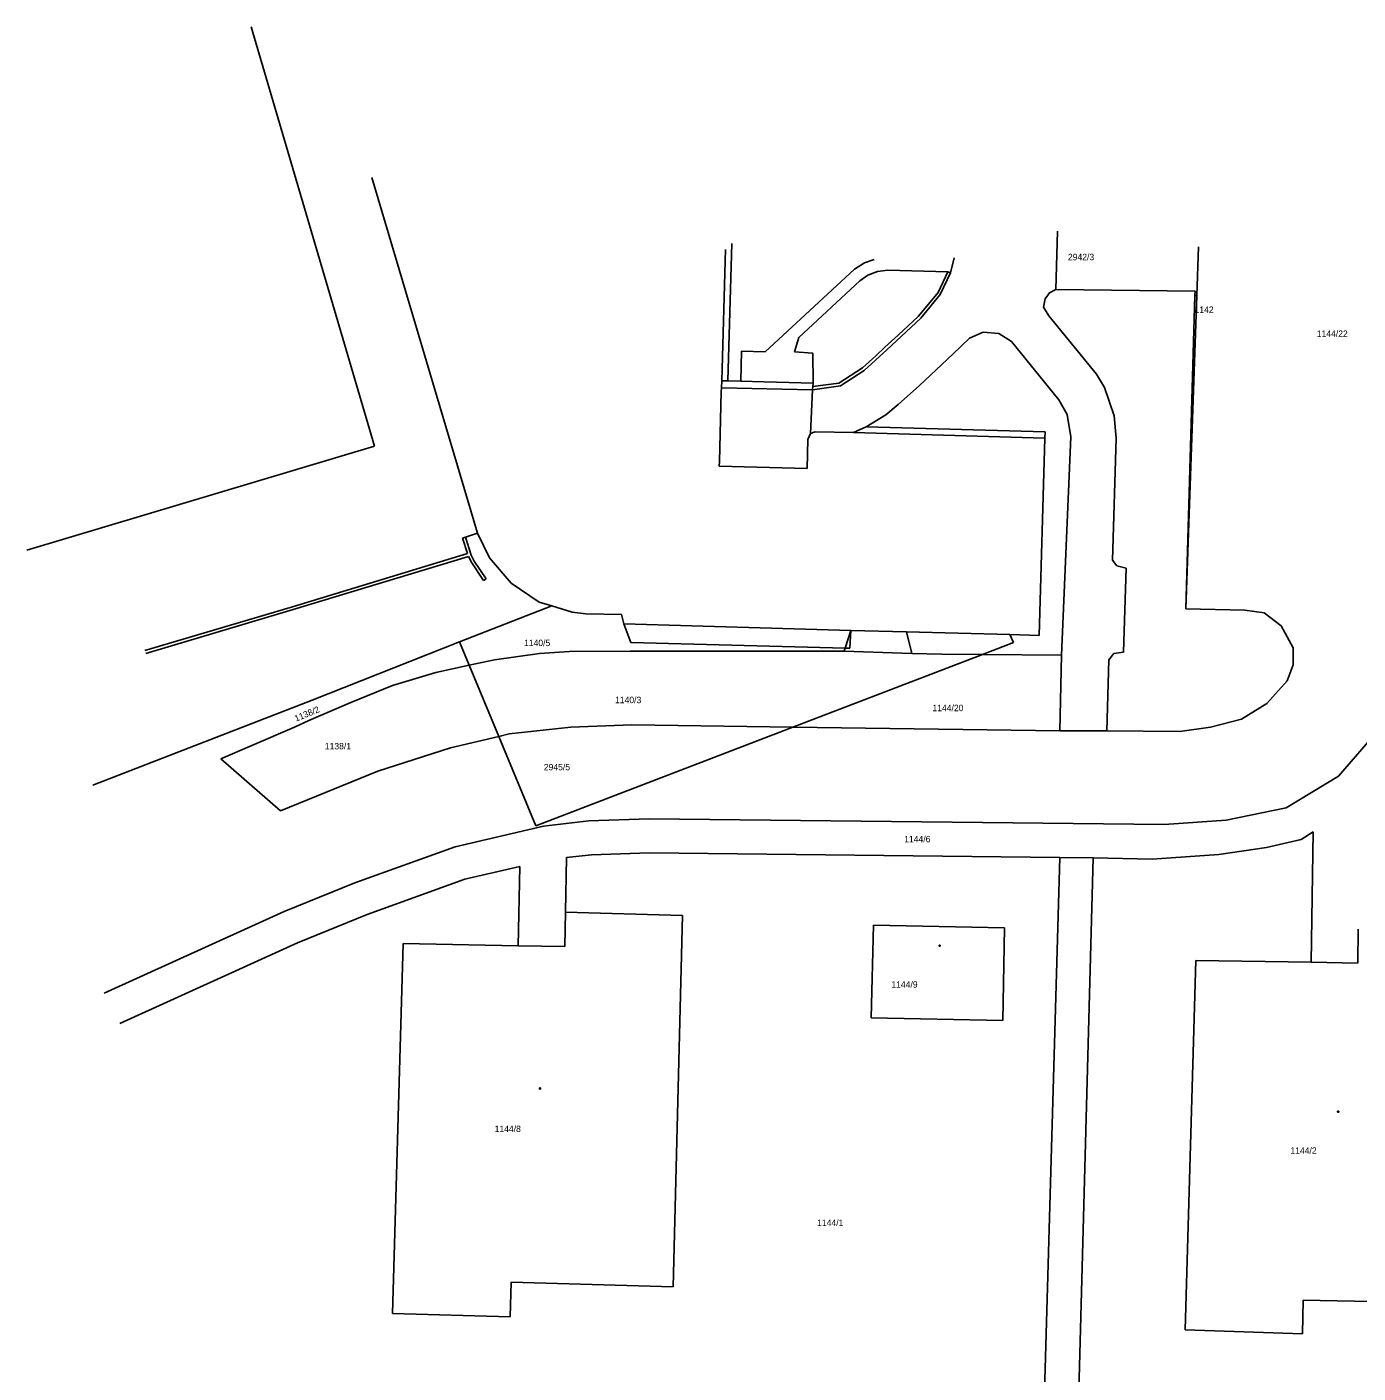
# Model space of a CAD drawing. Extents: x -609709 to -609357, y -1051535 to -1051131.
# Drawn here: x -609705.8 to -609617.6, y -1051228.1 to -1051138.9 of the extents above; entities that cross this region are included whole.
import ezdxf

# ---------------------------------------------------------------- set-up
doc = ezdxf.new("R2010")
doc.units = 0
doc.layers.add('Vrstva 10', color=7, linetype='Continuous')

msp = doc.modelspace()

# ---------------------------------------------------------------- linework, layer by layer
at = {"layer": 'Vrstva 10'}
for p, q in [((-609690.91, -1051138.88), (-609682.72, -1051166.66)), ((-609682.91, -1051148.86), (-609675.9, -1051172.42)), ((-609637.59, -1051156.27), (-609637.48, -1051152.42)), ((-609659.72, -1051162.34), (-609659.46, -1051153.63)), ((-609659.32, -1051162.34), (-609659.05, -1051153.24)), ((-609628.23, -1051156.67), (-609628.12, -1051153.46)), ((-609656.84, -1051160.41), (-609650.92, -1051154.94)), ((-609650.92, -1051154.94), (-609650.25, -1051154.52)), ((-609650.25, -1051154.52), (-609649.61, -1051154.3)), ((-609644.57, -1051155.17), (-609644.32, -1051154.19)), ((-609654.61, -1051159.46), (-609650.58, -1051155.71)), ((-609650.58, -1051155.71), (-609650.05, -1051155.32)), ((-609650.05, -1051155.32), (-609649.41, -1051155.08)), ((-609649.41, -1051155.08), (-609648.71, -1051154.99)), ((-609648.71, -1051154.99), (-609644.74, -1051155.1)), ((-609645.39, -1051156.48), (-609644.74, -1051155.1)), ((-609645.24, -1051156.61), (-609644.57, -1051155.17)), ((-609644.74, -1051155.1), (-609644.57, -1051155.17)), ((-609646.68, -1051158.04), (-609645.39, -1051156.48)), ((-609646.53, -1051158.17), (-609645.24, -1051156.61)), ((-609638.29, -1051156.9), (-609638, -1051156.5)), ((-609638, -1051156.5), (-609637.59, -1051156.27)), ((-609637.59, -1051156.27), (-609628.36, -1051156.39)), ((-609628.96, -1051177.44), (-609628.23, -1051156.67)), ((-609628.96, -1051177.44), (-609628.37, -1051156.67)), ((-609628.37, -1051156.67), (-609628.36, -1051156.39)), ((-609628.37, -1051156.67), (-609628.23, -1051156.67)), ((-609638.4, -1051157.45), (-609638.29, -1051156.9)), ((-609638.4, -1051157.45), (-609638.04, -1051158.03)), ((-609648.78, -1051160.28), (-609646.53, -1051158.17)), ((-609648.03, -1051159.31), (-609646.68, -1051158.04)), ((-609638.04, -1051158.03), (-609634.89, -1051161.9)), ((-609648.91, -1051160.11), (-609648.03, -1051159.31)), ((-609643.31, -1051159.5), (-609642.4, -1051159.11)), ((-609642.4, -1051159.11), (-609641.36, -1051159.2)), ((-609641.36, -1051159.2), (-609640.51, -1051159.73)), ((-609654.89, -1051160.42), (-609654.61, -1051159.46)), ((-609650.28, -1051161.64), (-609648.78, -1051160.28)), ((-609649.52, -1051160.67), (-609648.91, -1051160.11)), ((-609644.4, -1051160.56), (-609643.31, -1051159.5)), ((-609640.51, -1051159.73), (-609637.39, -1051163.58)), ((-609658.46, -1051162.36), (-609658.4, -1051160.36)), ((-609658.4, -1051160.36), (-609656.84, -1051160.41)), ((-609654.89, -1051160.42), (-609653.69, -1051160.5)), ((-609653.69, -1051160.5), (-609653.67, -1051162.48)), ((-609650.39, -1051161.47), (-609649.52, -1051160.67)), ((-609646.61, -1051162.65), (-609644.4, -1051160.56)), ((-609651.97, -1051162.49), (-609650.39, -1051161.47)), ((-609651.86, -1051162.66), (-609650.28, -1051161.64)), ((-609634.89, -1051161.9), (-609634.36, -1051162.77)), ((-609659.75, -1051163.07), (-609659.73, -1051162.8)), ((-609659.73, -1051162.8), (-609659.72, -1051162.34)), ((-609659.73, -1051162.8), (-609653.71, -1051162.93)), ((-609659.72, -1051162.34), (-609659.32, -1051162.34)), ((-609659.32, -1051162.34), (-609658.46, -1051162.36)), ((-609658.46, -1051162.36), (-609656.93, -1051162.39)), ((-609656.93, -1051162.39), (-609655.26, -1051162.45)), ((-609655.26, -1051162.45), (-609653.67, -1051162.48)), ((-609653.84, -1051165.82), (-609653.71, -1051162.93)), ((-609653.71, -1051162.93), (-609651.86, -1051162.66)), ((-609653.71, -1051162.93), (-609653.69, -1051162.7)), ((-609653.69, -1051162.7), (-609653.67, -1051162.48)), ((-609653.69, -1051162.7), (-609651.97, -1051162.49)), ((-609648.02, -1051163.9), (-609646.61, -1051162.65)), ((-609634.36, -1051162.77), (-609633.71, -1051164.66)), ((-609659.87, -1051167.67), (-609659.75, -1051163.07)), ((-609637.39, -1051163.58), (-609636.84, -1051164.56)), ((-609650.15, -1051165.39), (-609648.85, -1051164.58)), ((-609648.85, -1051164.58), (-609648.02, -1051163.9)), ((-609636.84, -1051164.56), (-609636.59, -1051166.05)), ((-609633.71, -1051164.66), (-609633.59, -1051166.14)), ((-609650.99, -1051165.76), (-609650.15, -1051165.39)), ((-609650.15, -1051165.39), (-609638.3, -1051165.72)), ((-609654.07, -1051168.15), (-609654.02, -1051166.21)), ((-609654.02, -1051166.21), (-609653.84, -1051165.82)), ((-609653.84, -1051165.82), (-609653.52, -1051165.72)), ((-609653.52, -1051165.72), (-609650.99, -1051165.76)), ((-609650.99, -1051165.76), (-609638.32, -1051166.12)), ((-609638.69, -1051179.2), (-609638.32, -1051166.12)), ((-609638.32, -1051166.12), (-609638.3, -1051165.72)), ((-609637.2, -1051180.5), (-609636.59, -1051166.05)), ((-609633.82, -1051174.22), (-609633.59, -1051166.14)), ((-609705.76, -1051173.56), (-609682.72, -1051166.66)), ((-609659.88, -1051167.99), (-609659.87, -1051167.67)), ((-609659.88, -1051167.99), (-609654.07, -1051168.15)), ((-609676.9, -1051172.76), (-609676.71, -1051172.69)), ((-609676.9, -1051172.76), (-609676.57, -1051173.77)), ((-609676.71, -1051172.69), (-609675.9, -1051172.42)), ((-609676.71, -1051172.69), (-609676.32, -1051173.88)), ((-609675.9, -1051172.42), (-609675.11, -1051174.06)), ((-609688.17, -1051177.3), (-609676.57, -1051173.77)), ((-609688.11, -1051177.49), (-609676.5, -1051173.97)), ((-609676.5, -1051173.97), (-609676.29, -1051174.4)), ((-609676.32, -1051173.88), (-609676.13, -1051174.29)), ((-609676.29, -1051174.4), (-609675.51, -1051175.56)), ((-609676.13, -1051174.29), (-609675.34, -1051175.45)), ((-609675.11, -1051174.06), (-609673.67, -1051175.74)), ((-609633.82, -1051174.22), (-609633.55, -1051174.59)), ((-609675.51, -1051175.56), (-609675.34, -1051175.45)), ((-609633.55, -1051174.59), (-609632.93, -1051174.74)), ((-609633.09, -1051180.31), (-609632.93, -1051174.74)), ((-609673.67, -1051175.74), (-609671.81, -1051177)), ((-609671.81, -1051177), (-609670.97, -1051177.25)), ((-609697.94, -1051180.21), (-609688.17, -1051177.3)), ((-609697.89, -1051180.4), (-609688.11, -1051177.49)), ((-609677.1, -1051179.63), (-609670.97, -1051177.25)), ((-609670.97, -1051177.25), (-609669.64, -1051177.65)), ((-609669.64, -1051177.65), (-609668.72, -1051177.78)), ((-609668.72, -1051177.78), (-609666.37, -1051177.81)), ((-609666.37, -1051177.81), (-609666.2, -1051178.44)), ((-609628.96, -1051177.44), (-609625.06, -1051177.52)), ((-609625.06, -1051177.52), (-609623.78, -1051177.7)), ((-609623.78, -1051177.7), (-609622.65, -1051178.57)), ((-609666.2, -1051178.44), (-609665.75, -1051179.68)), ((-609666.2, -1051178.44), (-609651.17, -1051178.87)), ((-609651.55, -1051180.04), (-609651.17, -1051178.87)), ((-609651.24, -1051180.05), (-609651.17, -1051178.87)), ((-609651.17, -1051178.87), (-609647.47, -1051178.96)), ((-609647.47, -1051178.96), (-609647.12, -1051180.39)), ((-609647.47, -1051178.96), (-609640.62, -1051179.15)), ((-609622.65, -1051178.57), (-609621.86, -1051180.03)), ((-609686.86, -1051183.49), (-609677.1, -1051179.63)), ((-609677.1, -1051179.63), (-609676.45, -1051181.18)), ((-609665.75, -1051179.68), (-609651.55, -1051180.04)), ((-609642.45, -1051180.46), (-609640.39, -1051179.67)), ((-609640.62, -1051179.15), (-609640.39, -1051179.67)), ((-609640.62, -1051179.15), (-609638.69, -1051179.2)), ((-609674.77, -1051180.82), (-609671.8, -1051180.4)), ((-609671.8, -1051180.4), (-609669.81, -1051180.26)), ((-609669.81, -1051180.26), (-609665.79, -1051180.25)), ((-609665.79, -1051180.25), (-609651.61, -1051180.24)), ((-609655.01, -1051185.28), (-609642.45, -1051180.46)), ((-609651.61, -1051180.24), (-609651.55, -1051180.04)), ((-609651.61, -1051180.24), (-609647.12, -1051180.39)), ((-609651.55, -1051180.04), (-609651.24, -1051180.05)), ((-609647.12, -1051180.39), (-609645.13, -1051180.44)), ((-609645.13, -1051180.44), (-609642.45, -1051180.46)), ((-609642.45, -1051180.46), (-609637.2, -1051180.5)), ((-609637.32, -1051185.53), (-609637.2, -1051180.5)), ((-609634.2, -1051185.52), (-609634.06, -1051180.81)), ((-609634.06, -1051180.81), (-609633.73, -1051180.39)), ((-609633.73, -1051180.39), (-609633.09, -1051180.31)), ((-609621.86, -1051180.03), (-609621.86, -1051181.15)), ((-609681.53, -1051182.51), (-609678.66, -1051181.66)), ((-609678.66, -1051181.66), (-609676.45, -1051181.18)), ((-609676.45, -1051181.18), (-609674.77, -1051180.82)), ((-609676.45, -1051181.18), (-609674.49, -1051185.89)), ((-609622.26, -1051182.21), (-609621.86, -1051181.15)), ((-609684.3, -1051183.65), (-609681.53, -1051182.51)), ((-609623.6, -1051183.71), (-609622.26, -1051182.21)), ((-609701.4, -1051189.13), (-609686.86, -1051183.49)), ((-609687.08, -1051184.84), (-609685.23, -1051184.04)), ((-609685.23, -1051184.04), (-609684.3, -1051183.65)), ((-609625.28, -1051184.75), (-609623.6, -1051183.71)), ((-609690.86, -1051186.49), (-609688.02, -1051185.27)), ((-609688.02, -1051185.27), (-609687.08, -1051184.84)), ((-609669.73, -1051185.29), (-609665.67, -1051185.13)), ((-609665.67, -1051185.13), (-609655.01, -1051185.28)), ((-609627.33, -1051185.28), (-609625.28, -1051184.75)), ((-609677.69, -1051186.65), (-609674.49, -1051185.89)), ((-609674.49, -1051185.89), (-609673.81, -1051185.73)), ((-609674.49, -1051185.89), (-609672.03, -1051191.81)), ((-609673.81, -1051185.73), (-609669.73, -1051185.29)), ((-609672.03, -1051191.81), (-609655.01, -1051185.28)), ((-609655.01, -1051185.28), (-609637.32, -1051185.53)), ((-609637.32, -1051185.53), (-609634.2, -1051185.52)), ((-609634.2, -1051185.52), (-609629.37, -1051185.56)), ((-609629.37, -1051185.56), (-609627.33, -1051185.28)), ((-609618.86, -1051188.53), (-609616.18, -1051185.43)), ((-609692.91, -1051187.37), (-609690.86, -1051186.49)), ((-609682.5, -1051188.19), (-609677.69, -1051186.65)), ((-609692.91, -1051187.37), (-609688.95, -1051190.83)), ((-609688.95, -1051190.83), (-609682.5, -1051188.19)), ((-609622.33, -1051190.62), (-609618.86, -1051188.53)), ((-609626.29, -1051191.44), (-609622.33, -1051190.62)), ((-609671.53, -1051191.83), (-609668.52, -1051191.48)), ((-609668.52, -1051191.48), (-609664.53, -1051191.36)), ((-609664.53, -1051191.36), (-609630.41, -1051191.74)), ((-609630.41, -1051191.74), (-609626.29, -1051191.44)), ((-609677.39, -1051193.2), (-609671.53, -1051191.83)), ((-609621.33, -1051192.72), (-609620.53, -1051192.22)), ((-609620.67, -1051200.86), (-609620.53, -1051192.22)), ((-609684.03, -1051195.6), (-609677.39, -1051193.2)), ((-609626.79, -1051193.72), (-609623.63, -1051193.25)), ((-609623.63, -1051193.25), (-609621.33, -1051192.72)), ((-609670.07, -1051197.54), (-609670.01, -1051193.92)), ((-609670.01, -1051193.92), (-609668.36, -1051193.73)), ((-609668.36, -1051193.73), (-609664.51, -1051193.61)), ((-609664.51, -1051193.61), (-609637.32, -1051193.91)), ((-609638.79, -1051244.97), (-609637.32, -1051193.91)), ((-609637.32, -1051193.91), (-609635.11, -1051193.94)), ((-609636.49, -1051245.01), (-609635.11, -1051193.94)), ((-609635.11, -1051193.94), (-609631.2, -1051194.03)), ((-609631.2, -1051194.03), (-609626.79, -1051193.72)), ((-609676.75, -1051195.36), (-609673.1, -1051194.51)), ((-609673.2, -1051199.76), (-609673.1, -1051194.51)), ((-609688.71, -1051197.49), (-609684.03, -1051195.6)), ((-609683.22, -1051197.7), (-609676.75, -1051195.36)), ((-609700.64, -1051202.9), (-609688.71, -1051197.49)), ((-609687.82, -1051199.56), (-609683.22, -1051197.7)), ((-609670.11, -1051199.81), (-609670.07, -1051197.54)), ((-609670.07, -1051197.54), (-609662.32, -1051197.76)), ((-609662.94, -1051222.36), (-609662.32, -1051197.76)), ((-609649.82, -1051204.53), (-609649.67, -1051198.4)), ((-609649.67, -1051198.4), (-609640.99, -1051198.58)), ((-609641.1, -1051204.71), (-609640.99, -1051198.58)), ((-609617.57, -1051200.91), (-609617.54, -1051198.66)), ((-609699.61, -1051204.91), (-609687.82, -1051199.56)), ((-609681.53, -1051224.13), (-609680.83, -1051199.62)), ((-609680.83, -1051199.62), (-609673.2, -1051199.76)), ((-609673.2, -1051199.76), (-609670.11, -1051199.81)), ((-609645.315, -1051199.725), (-609645.24, -1051199.725)), ((-609645.315, -1051199.8), (-609645.315, -1051199.725)), ((-609645.24, -1051199.8), (-609645.315, -1051199.8)), ((-609645.24, -1051199.725), (-609645.24, -1051199.8)), ((-609629.01, -1051225.21), (-609628.3, -1051200.75)), ((-609628.3, -1051200.75), (-609620.67, -1051200.86)), ((-609620.67, -1051200.86), (-609617.57, -1051200.91)), ((-609649.82, -1051204.53), (-609641.1, -1051204.71)), ((-609671.805, -1051209.185), (-609671.73, -1051209.185)), ((-609671.805, -1051209.26), (-609671.805, -1051209.185)), ((-609671.73, -1051209.26), (-609671.805, -1051209.26)), ((-609671.73, -1051209.185), (-609671.73, -1051209.26)), ((-609618.915, -1051210.715), (-609618.84, -1051210.715)), ((-609618.915, -1051210.79), (-609618.915, -1051210.715)), ((-609618.84, -1051210.79), (-609618.915, -1051210.79)), ((-609618.84, -1051210.715), (-609618.84, -1051210.79)), ((-609673.73, -1051224.35), (-609673.67, -1051222.05)), ((-609673.67, -1051222.05), (-609662.94, -1051222.36)), ((-609621.24, -1051225.49), (-609621.19, -1051223.24)), ((-609621.19, -1051223.24), (-609610.56, -1051223.48)), ((-609681.53, -1051224.13), (-609673.73, -1051224.35)), ((-609629.01, -1051225.21), (-609621.24, -1051225.49))]:
    msp.add_line(p, q, dxfattribs=at)

# ---------------------------------------------------------------- texts
for s, p in [('2942/3', (-609636.78, -1051154.34)), ('1142', (-609628.39, -1051157.83)), ('1144/22', (-609620.293, -1051159.42)), ('1140/5', (-609672.82, -1051179.91)), ('1140/3', (-609666.79, -1051183.69)), ('1144/20', (-609645.76, -1051184.22)), ('1138/1', (-609686.02, -1051186.75)), ('2945/5', (-609671.51, -1051188.14)), ('1144/6', (-609647.63, -1051192.91)), ('1144/9', (-609648.48, -1051202.54)), ('1144/8', (-609674.77, -1051212.11)), ('1144/2', (-609622.04, -1051213.55)), ('1144/1', (-609653.4, -1051218.33))]:
    msp.add_text(s, height=0.425, dxfattribs=at).set_placement(p)
msp.add_text('1138/2', height=0.425, rotation=22.31559, dxfattribs=at).set_placement((-609687.928, -1051184.92))

doc.saveas('drawing.dxf')
